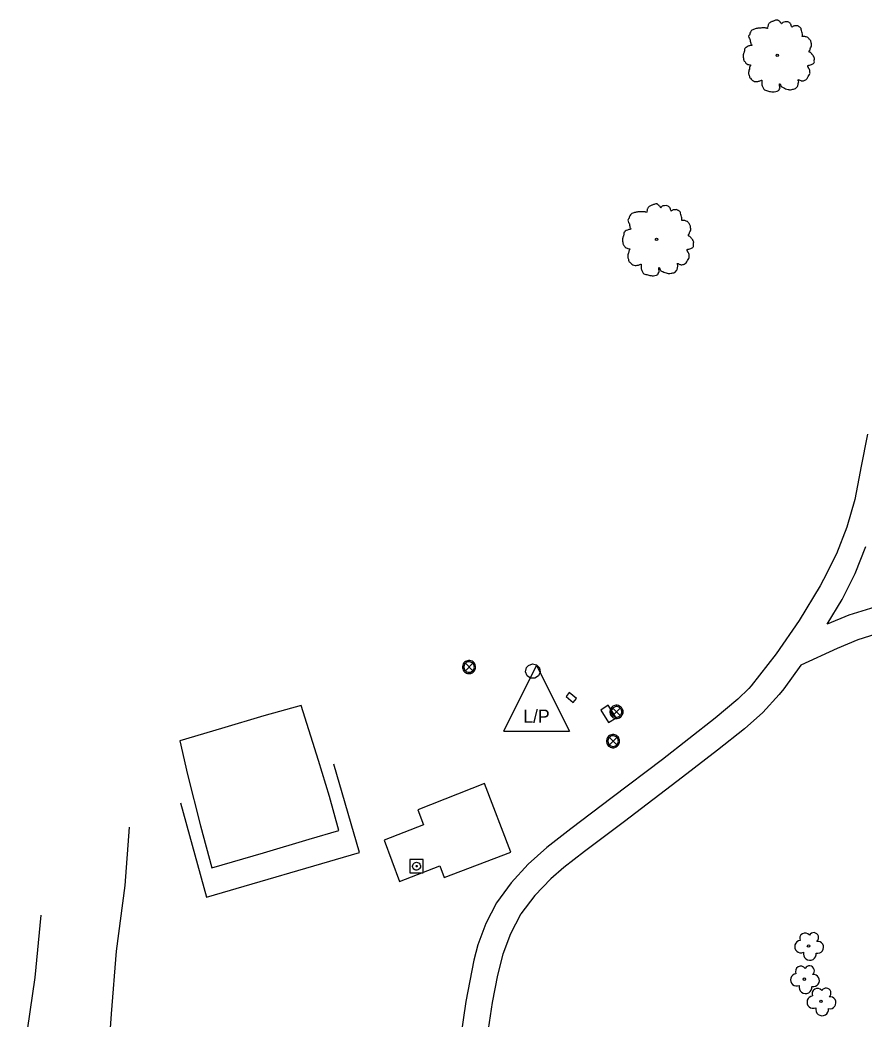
# Model space of a CAD drawing. Extents: x 2161152 to 2175754, y 602179 to 617749.
# Drawn here: x 2162053.8 to 2162182.3, y 604496.4 to 604648.6 of the extents above; entities that cross this region are included whole.
import ezdxf

# ---------------------------------------------------------------- set-up
doc = ezdxf.new("R2010")
doc.units = 0
for name, color, linetype in [('RD_EX_BldgApp', 7, 'Continuous'), ('RD_EX_BldgApp_Post', 7, 'Continuous'), ('RD_EX_Conc_Sidewalk', 7, 'Continuous'), ('RD_EX_Conc_Slab', 7, 'Continuous'), ('RD_EX_Fence_Other', 7, 'Continuous'), ('RD_EX_Misc', 7, 'Continuous'), ('RD_EX_Parking_Asphalt', 7, 'Continuous'), ('RD_EX_UT', 7, 'Continuous'), ('RD_EX_VEG', 7, 'Continuous')]:
    doc.layers.add(name, color=color, linetype=linetype)

msp = doc.modelspace()

# ---------------------------------------------------------------- linework, layer by layer
at = {"layer": 'RD_EX_BldgApp'}
msp.add_lwpolyline([(2162132.75, 604548.7), (2162132.21, 604548.34), (2162131.55, 604548.34), (2162131.02, 604548.71), (2162130.78, 604549.32), (2162130.92, 604549.95), (2162131.22, 604550.29), (2162131.83, 604550.52), (2162132.46, 604550.37), (2162132.9, 604549.89), (2162132.99, 604549.24), (2162132.75, 604548.7)], dxfattribs=at)
at = {"layer": 'RD_EX_BldgApp_Post'}
for p, q in [((2162122.75, 604549.47), (2162121.62, 604550.6)), ((2162121.62, 604549.47), (2162122.75, 604550.6)), ((2162145.21, 604542.64), (2162144.07, 604543.78)), ((2162144.07, 604542.64), (2162145.21, 604543.78)), ((2162144.68, 604538.18), (2162143.55, 604539.32)), ((2162143.55, 604538.18), (2162144.68, 604539.32))]:
    msp.add_line(p, q, dxfattribs=at)
for points in [[(2162123.19, 604550.03), (2162123.18, 604550.19), (2162123.14, 604550.35), (2162123.06, 604550.51), (2162122.96, 604550.67), (2162122.82, 604550.81), (2162122.66, 604550.92), (2162122.48, 604550.99), (2162122.29, 604551.03), (2162122.1, 604551.03), (2162121.93, 604551), (2162121.78, 604550.95), (2162121.64, 604550.87), (2162121.51, 604550.78), (2162121.4, 604550.65), (2162121.3, 604550.5), (2162121.23, 604550.32), (2162121.19, 604550.13), (2162121.19, 604549.93), (2162121.23, 604549.74), (2162121.3, 604549.57), (2162121.4, 604549.41), (2162121.51, 604549.29), (2162121.64, 604549.19), (2162121.78, 604549.12), (2162121.93, 604549.06), (2162122.1, 604549.03), (2162122.29, 604549.04), (2162122.48, 604549.07), (2162122.66, 604549.15), (2162122.82, 604549.26), (2162122.96, 604549.4), (2162123.06, 604549.55), (2162123.14, 604549.72), (2162123.18, 604549.88), (2162123.19, 604550.03)], [(2162122.99, 604550.03), (2162122.98, 604550.16), (2162122.95, 604550.29), (2162122.89, 604550.42), (2162122.8, 604550.54), (2162122.69, 604550.65), (2162122.56, 604550.74), (2162122.42, 604550.8), (2162122.27, 604550.83), (2162122.12, 604550.83), (2162121.98, 604550.81), (2162121.86, 604550.76), (2162121.75, 604550.71), (2162121.65, 604550.63), (2162121.56, 604550.53), (2162121.48, 604550.41), (2162121.42, 604550.27), (2162121.39, 604550.11), (2162121.39, 604549.95), (2162121.42, 604549.8), (2162121.48, 604549.66), (2162121.56, 604549.54), (2162121.65, 604549.44), (2162121.75, 604549.36), (2162121.86, 604549.3), (2162121.98, 604549.26), (2162122.12, 604549.23), (2162122.27, 604549.24), (2162122.42, 604549.27), (2162122.56, 604549.33), (2162122.69, 604549.41), (2162122.8, 604549.52), (2162122.89, 604549.65), (2162122.95, 604549.78), (2162122.98, 604549.91), (2162122.99, 604550.03)], [(2162145.64, 604543.21), (2162145.63, 604543.36), (2162145.59, 604543.53), (2162145.52, 604543.69), (2162145.41, 604543.85), (2162145.28, 604543.98), (2162145.11, 604544.09), (2162144.93, 604544.17), (2162144.74, 604544.21), (2162144.56, 604544.21), (2162144.38, 604544.18), (2162144.23, 604544.12), (2162144.1, 604544.05), (2162143.97, 604543.95), (2162143.85, 604543.83), (2162143.75, 604543.68), (2162143.68, 604543.5), (2162143.64, 604543.31), (2162143.64, 604543.11), (2162143.68, 604542.92), (2162143.75, 604542.74), (2162143.85, 604542.59), (2162143.97, 604542.46), (2162144.1, 604542.37), (2162144.23, 604542.29), (2162144.38, 604542.24), (2162144.56, 604542.21), (2162144.74, 604542.21), (2162144.93, 604542.25), (2162145.11, 604542.32), (2162145.28, 604542.43), (2162145.41, 604542.57), (2162145.52, 604542.73), (2162145.59, 604542.89), (2162145.63, 604543.05), (2162145.64, 604543.21)], [(2162145.44, 604543.21), (2162145.43, 604543.33), (2162145.4, 604543.46), (2162145.34, 604543.59), (2162145.26, 604543.72), (2162145.15, 604543.83), (2162145.02, 604543.92), (2162144.87, 604543.98), (2162144.72, 604544.01), (2162144.57, 604544.01), (2162144.44, 604543.98), (2162144.31, 604543.94), (2162144.21, 604543.88), (2162144.1, 604543.81), (2162144.01, 604543.71), (2162143.93, 604543.58), (2162143.87, 604543.44), (2162143.84, 604543.29), (2162143.84, 604543.13), (2162143.87, 604542.98), (2162143.93, 604542.84), (2162144.01, 604542.71), (2162144.1, 604542.61), (2162144.21, 604542.54), (2162144.31, 604542.48), (2162144.44, 604542.43), (2162144.57, 604542.41), (2162144.72, 604542.41), (2162144.87, 604542.44), (2162145.02, 604542.5), (2162145.15, 604542.59), (2162145.26, 604542.7), (2162145.34, 604542.82), (2162145.4, 604542.96), (2162145.43, 604543.09), (2162145.44, 604543.21)], [(2162145.12, 604538.75), (2162145.1, 604538.9), (2162145.07, 604539.07), (2162144.99, 604539.23), (2162144.89, 604539.39), (2162144.75, 604539.52), (2162144.59, 604539.63), (2162144.4, 604539.71), (2162144.22, 604539.75), (2162144.03, 604539.75), (2162143.86, 604539.72), (2162143.7, 604539.66), (2162143.57, 604539.59), (2162143.44, 604539.49), (2162143.33, 604539.37), (2162143.23, 604539.22), (2162143.15, 604539.04), (2162143.12, 604538.85), (2162143.12, 604538.65), (2162143.15, 604538.46), (2162143.23, 604538.28), (2162143.33, 604538.13), (2162143.44, 604538), (2162143.57, 604537.91), (2162143.7, 604537.84), (2162143.86, 604537.78), (2162144.03, 604537.75), (2162144.22, 604537.75), (2162144.4, 604537.79), (2162144.59, 604537.87), (2162144.75, 604537.98), (2162144.89, 604538.11), (2162144.99, 604538.27), (2162145.07, 604538.43), (2162145.1, 604538.6), (2162145.12, 604538.75)], [(2162144.92, 604538.75), (2162144.91, 604538.87), (2162144.87, 604539), (2162144.82, 604539.13), (2162144.73, 604539.26), (2162144.62, 604539.37), (2162144.49, 604539.46), (2162144.35, 604539.52), (2162144.2, 604539.55), (2162144.05, 604539.55), (2162143.91, 604539.53), (2162143.79, 604539.48), (2162143.68, 604539.42), (2162143.58, 604539.35), (2162143.48, 604539.25), (2162143.4, 604539.12), (2162143.35, 604538.98), (2162143.32, 604538.83), (2162143.32, 604538.67), (2162143.35, 604538.52), (2162143.4, 604538.38), (2162143.48, 604538.25), (2162143.58, 604538.15), (2162143.68, 604538.08), (2162143.79, 604538.02), (2162143.91, 604537.97), (2162144.05, 604537.95), (2162144.2, 604537.95), (2162144.35, 604537.98), (2162144.49, 604538.04), (2162144.62, 604538.13), (2162144.73, 604538.24), (2162144.82, 604538.37), (2162144.87, 604538.5), (2162144.91, 604538.63), (2162144.92, 604538.75)]]:
    msp.add_lwpolyline(points, dxfattribs=at)
at = {"layer": 'RD_EX_Conc_Sidewalk'}
for points in [[(2162182.89, 604585.49), (2162181.85, 604580.4), (2162181.76, 604579.84), (2162180.92, 604575.56), (2162179.7, 604571.36), (2162178.12, 604567.29), (2162176.19, 604563.38), (2162175.64, 604562.41), (2162172.46, 604557.12), (2162168.95, 604552.04), (2162165.14, 604547.19), (2162164.79, 604546.78), (2162163.13, 604545.12), (2162159.67, 604542.24), (2162151.66, 604535.96), (2162143.97, 604530.16), (2162137.67, 604525.39), (2162134.03, 604522.54), (2162131.18, 604520), (2162128.61, 604517.17), (2162126.34, 604514.1), (2162124.75, 604510.99), (2162123.53, 604507.73), (2162122.89, 604505.36), (2162121.7, 604499.1), (2162120.07, 604487.93)], [(2162183.99, 604559.14), (2162180.04, 604557.93), (2162176.72, 604556.54), (2162179.02, 604560.31), (2162180.99, 604564.27), (2162182.62, 604568.38)], [(2162184.94, 604555.28), (2162181.39, 604554.2), (2162178.25, 604552.88), (2162172.69, 604550.3), (2162170.11, 604546.73), (2162169.43, 604545.87), (2162166.92, 604543.11), (2162164.13, 604540.62), (2162160.02, 604537.36), (2162154.69, 604533.24), (2162145.85, 604526.49), (2162139.77, 604521.91), (2162136.62, 604519.49), (2162134.65, 604517.78), (2162132.22, 604515.23), (2162130.09, 604512.43), (2162130.03, 604512.32), (2162128.49, 604509.4), (2162127.31, 604506.31), (2162126.51, 604503.11), (2162125.68, 604498.95), (2162124.2, 604488.77)]]:
    msp.add_lwpolyline(points, dxfattribs=at)
at = {"layer": 'RD_EX_Conc_Slab'}
for points in [[(2162078.14, 604538.81), (2162079.29, 604533.65), (2162081.26, 604525.82), (2162083.03, 604519.46), (2162090.89, 604521.73), (2162097.82, 604523.82), (2162102.33, 604525.14), (2162100.92, 604530.32), (2162099.24, 604535.8), (2162096.63, 604544.18), (2162090.94, 604542.59), (2162084.5, 604540.69), (2162078.14, 604538.81)], [(2162109.28, 604523.66), (2162111.57, 604517.37), (2162117.72, 604519.76), (2162118.4, 604517.98), (2162128.57, 604521.83), (2162124.52, 604532.29), (2162114.37, 604528.29), (2162115.24, 604526), (2162109.28, 604523.66)]]:
    msp.add_lwpolyline(points, dxfattribs=at)
at = {"layer": 'RD_EX_Fence_Other'}
msp.add_lwpolyline([(2162078.24, 604529.36), (2162082.18, 604515), (2162105.52, 604521.77), (2162101.59, 604535.26)], dxfattribs=at)
at = {"layer": 'RD_EX_Misc'}
for points in [[(2162113.19, 604518.7), (2162115.19, 604518.7), (2162115.19, 604520.7), (2162113.19, 604520.7), (2162113.19, 604518.7)], [(2162113.59, 604519.7), (2162113.61, 604519.85), (2162113.67, 604519.99), (2162113.76, 604520.11), (2162113.88, 604520.21), (2162114.02, 604520.27), (2162114.17, 604520.3), (2162114.32, 604520.28), (2162114.47, 604520.23), (2162114.59, 604520.14), (2162114.69, 604520.02), (2162114.76, 604519.88), (2162114.79, 604519.73), (2162114.79, 604519.7)], [(2162114.79, 604519.7), (2162114.77, 604519.54), (2162114.71, 604519.4), (2162114.62, 604519.28), (2162114.5, 604519.18), (2162114.36, 604519.12), (2162114.21, 604519.1), (2162114.06, 604519.11), (2162113.91, 604519.16), (2162113.79, 604519.25), (2162113.69, 604519.37), (2162113.62, 604519.51), (2162113.59, 604519.66), (2162113.59, 604519.7)], [(2162114.09, 604519.7), (2162114.11, 604519.75), (2162114.16, 604519.79), (2162114.22, 604519.79), (2162114.27, 604519.75), (2162114.29, 604519.7)], [(2162114.29, 604519.7), (2162114.27, 604519.64), (2162114.22, 604519.6), (2162114.16, 604519.6), (2162114.11, 604519.64), (2162114.09, 604519.7)]]:
    msp.add_lwpolyline(points, dxfattribs=at)
at = {"layer": 'RD_EX_Parking_Asphalt'}
for points in [[(2162066.8, 604484.24), (2162067.74, 604497.21), (2162068.47, 604506.77), (2162069.79, 604516.75), (2162070.47, 604525.63)], [(2162056.95, 604512.25), (2162056.05, 604502.75), (2162053.79, 604487.07)]]:
    msp.add_lwpolyline(points, dxfattribs=at)
at = {"layer": 'RD_EX_UT'}
for p, q in [((2162127.46, 604540.27), (2162132.46, 604550.27)), ((2162132.46, 604550.27), (2162137.46, 604540.27)), ((2162127.46, 604540.27), (2162137.46, 604540.27))]:
    msp.add_line(p, q, dxfattribs=at)
for points in [[(2162136.96, 604545.54), (2162138.06, 604544.65), (2162138.56, 604545.26), (2162137.45, 604546.15), (2162136.96, 604545.54)], [(2162142.23, 604543.48), (2162143.43, 604541.57), (2162144.59, 604542.29), (2162143.39, 604544.21), (2162142.23, 604543.48)]]:
    msp.add_lwpolyline(points, dxfattribs=at)
at = {"layer": 'RD_EX_VEG'}
for centre, radius in [((2162169.12, 604643.2), 0.188), ((2162169.11, 604643.18), 0.000075), ((2162150.74, 604615.19), 0.188), ((2162150.73, 604615.18), 0.000075), ((2162173.89, 604507.55), 0.188), ((2162173.25, 604502.49), 0.188), ((2162175.77, 604499.11), 0.188)]:
    msp.add_circle(centre, radius, dxfattribs=at)
for centre, radius, start, end in [((2162173.35, 604508.71), 0.813, 34.9763, 204.756), ((2162174.68, 604508.83), 0.746, 308.7626, 152.0467), ((2162172.72, 604507.44), 0.943, 96.4518, 294.734), ((2162175.27, 604507.34), 0.914, 256.5667, 98.1046), ((2162174.08, 604506.36), 0.988, 166.8827, 5.7589), ((2162174.03, 604503.77), 0.746, 308.7626, 152.0467), ((2162172.08, 604502.38), 0.943, 96.4518, 294.734), ((2162172.71, 604503.65), 0.813, 34.9763, 204.756), ((2162174.63, 604502.28), 0.914, 256.5667, 98.1046), ((2162173.43, 604501.29), 0.988, 166.8827, 5.7589), ((2162174.6, 604498.99), 0.943, 96.4518, 294.734), ((2162175.23, 604500.27), 0.813, 34.9763, 204.756), ((2162176.56, 604500.38), 0.746, 308.7626, 152.0467), ((2162177.15, 604498.9), 0.914, 256.5667, 98.1046), ((2162175.96, 604497.91), 0.988, 166.8827, 5.7589)]:
    msp.add_arc(centre, radius, start, end, dxfattribs=at)
for points in [[(2162169.22, 604648.57), (2162168.99, 604648.59), (2162168.75, 604648.52), (2162168.56, 604648.44), (2162168.39, 604648.39), (2162168.23, 604648.31), (2162168, 604648.18), (2162167.83, 604648.03), (2162167.74, 604647.84), (2162167.7, 604647.67), (2162167.66, 604647.47), (2162167.66, 604647.34), (2162167.57, 604647.32), (2162167.46, 604647.34), (2162167.27, 604647.39), (2162167.08, 604647.39), (2162166.9, 604647.39), (2162166.63, 604647.37), (2162166.37, 604647.37), (2162166.16, 604647.34), (2162165.92, 604647.3), (2162165.64, 604647.2), (2162165.38, 604647.11), (2162165.15, 604646.92), (2162164.96, 604646.57), (2162164.87, 604646.3), (2162164.76, 604646.12), (2162164.87, 604645.78), (2162165, 604645.52), (2162165.02, 604645.37), (2162165.08, 604645.05), (2162165.15, 604644.88), (2162165.25, 604644.73), (2162165.19, 604644.71), (2162164.91, 604644.67), (2162164.68, 604644.6), (2162164.37, 604644.43), (2162164.2, 604644.26), (2162164.12, 604644.02), (2162164.1, 604643.76), (2162164.03, 604643.61), (2162163.97, 604643.4), (2162163.95, 604643.34), (2162163.92, 604643.1), (2162163.99, 604642.76), (2162164.01, 604642.5), (2162164.1, 604642.33), (2162164.22, 604642.2), (2162164.35, 604642.01), (2162164.65, 604641.84), (2162164.89, 604641.77), (2162165.04, 604641.75), (2162164.91, 604641.38), (2162164.87, 604641.11), (2162164.78, 604640.81), (2162164.78, 604640.76), (2162164.74, 604640.4), (2162164.85, 604640.16), (2162164.91, 604639.88), (2162165.04, 604639.71), (2162165.25, 604639.48), (2162165.49, 604639.31), (2162165.86, 604639.22), (2162166.16, 604639.24), (2162166.6, 604639.37), (2162166.78, 604639.43), (2162166.76, 604639.3), (2162166.78, 604639.01), (2162166.78, 604638.7), (2162166.9, 604638.45), (2162166.97, 604638.25), (2162167.08, 604638.06), (2162167.33, 604637.89), (2162167.63, 604637.83), (2162167.94, 604637.72), (2162168.28, 604637.66), (2162168.66, 604637.65), (2162169.11, 604637.76), (2162169.31, 604637.85), (2162169.39, 604637.98), (2162169.54, 604638.26), (2162169.5, 604638.43), (2162169.52, 604638.88), (2162169.59, 604638.75), (2162169.73, 604638.49), (2162170.1, 604638.26), (2162170.4, 604638.13), (2162170.76, 604638.02), (2162170.98, 604637.96), (2162171.34, 604638.02), (2162171.62, 604638.08), (2162171.9, 604638.17), (2162172.12, 604638.38), (2162172.26, 604638.58), (2162172.29, 604638.79), (2162172.35, 604639.07), (2162172.39, 604639.2)], [(2162172.39, 604639.2), (2162172.33, 604639.33), (2162172.29, 604639.52), (2162172.35, 604639.5), (2162172.48, 604639.46), (2162172.69, 604639.37), (2162172.86, 604639.31), (2162173.1, 604639.33), (2162173.31, 604639.41), (2162173.64, 604639.61), (2162173.85, 604639.97), (2162174.05, 604640.27), (2162174.11, 604640.51), (2162174.07, 604640.68), (2162174.05, 604641.06), (2162173.9, 604641.24), (2162173.87, 604641.34), (2162173.79, 604641.64), (2162173.85, 604641.68), (2162174.05, 604641.71), (2162174.34, 604641.81), (2162174.54, 604641.9), (2162174.71, 604642.03), (2162174.77, 604642.2), (2162174.75, 604642.5), (2162174.79, 604642.8), (2162174.73, 604642.91), (2162174.65, 604643.02), (2162174.6, 604643.17), (2162174.49, 604643.29), (2162174.41, 604643.4), (2162174.34, 604643.47), (2162174.24, 604643.59), (2162174.11, 604643.68), (2162174, 604643.72), (2162173.96, 604643.83), (2162174.07, 604643.98), (2162174.11, 604644.06), (2162174.13, 604644.22), (2162174.3, 604644.49), (2162174.34, 604644.79), (2162174.3, 604645.11), (2162174.26, 604645.31), (2162174.15, 604645.52), (2162174, 604645.7), (2162173.9, 604645.84), (2162173.77, 604645.93), (2162173.53, 604646.02), (2162173.34, 604646.06), (2162173.08, 604646.06), (2162172.93, 604646.1), (2162172.95, 604646.14), (2162172.95, 604646.25), (2162172.95, 604646.45), (2162172.89, 604646.79), (2162172.78, 604647.17), (2162172.78, 604647.19), (2162172.71, 604647.37), (2162172.54, 604647.52), (2162172.41, 604647.6), (2162172.26, 604647.69), (2162172.07, 604647.71), (2162171.84, 604647.71), (2162171.64, 604647.67), (2162171.49, 604647.6), (2162171.36, 604647.5), (2162171.3, 604647.62), (2162171.22, 604647.84), (2162171.19, 604647.95), (2162171.07, 604648.09), (2162170.91, 604648.24), (2162170.57, 604648.33), (2162170.1, 604648.27), (2162169.88, 604648.12), (2162169.76, 604647.99), (2162169.73, 604648.09), (2162169.58, 604648.24), (2162169.5, 604648.37), (2162169.37, 604648.46), (2162169.26, 604648.53), (2162169.18, 604648.57)], [(2162150.84, 604620.57), (2162150.61, 604620.58), (2162150.37, 604620.51), (2162150.18, 604620.43), (2162150.01, 604620.38), (2162149.84, 604620.3), (2162149.62, 604620.17), (2162149.45, 604620.02), (2162149.35, 604619.84), (2162149.32, 604619.67), (2162149.28, 604619.46), (2162149.28, 604619.33), (2162149.19, 604619.31), (2162149.07, 604619.33), (2162148.89, 604619.39), (2162148.7, 604619.39), (2162148.51, 604619.39), (2162148.25, 604619.37), (2162147.99, 604619.37), (2162147.78, 604619.33), (2162147.54, 604619.29), (2162147.26, 604619.2), (2162146.99, 604619.1), (2162146.77, 604618.92), (2162146.58, 604618.56), (2162146.49, 604618.3), (2162146.37, 604618.11), (2162146.49, 604617.77), (2162146.62, 604617.51), (2162146.64, 604617.36), (2162146.69, 604617.04), (2162146.77, 604616.87), (2162146.86, 604616.72), (2162146.81, 604616.71), (2162146.52, 604616.67), (2162146.3, 604616.59), (2162145.98, 604616.42), (2162145.81, 604616.26), (2162145.74, 604616.01), (2162145.72, 604615.75), (2162145.64, 604615.6), (2162145.59, 604615.39), (2162145.57, 604615.34), (2162145.53, 604615.09), (2162145.61, 604614.76), (2162145.63, 604614.49), (2162145.72, 604614.33), (2162145.83, 604614.19), (2162145.96, 604614.01), (2162146.26, 604613.84), (2162146.51, 604613.76), (2162146.66, 604613.74), (2162146.52, 604613.37), (2162146.49, 604613.11), (2162146.39, 604612.81), (2162146.39, 604612.75), (2162146.36, 604612.39), (2162146.47, 604612.15), (2162146.52, 604611.87), (2162146.66, 604611.7), (2162146.86, 604611.48), (2162147.11, 604611.31), (2162147.48, 604611.21), (2162147.78, 604611.23), (2162148.21, 604611.36), (2162148.4, 604611.42), (2162148.38, 604611.29), (2162148.4, 604611.01), (2162148.4, 604610.69), (2162148.51, 604610.45), (2162148.59, 604610.24), (2162148.7, 604610.05), (2162148.94, 604609.88), (2162149.24, 604609.83), (2162149.56, 604609.71), (2162149.9, 604609.66), (2162150.27, 604609.64), (2162150.72, 604609.75), (2162150.93, 604609.85), (2162151, 604609.98), (2162151.15, 604610.26), (2162151.12, 604610.43), (2162151.14, 604610.88), (2162151.21, 604610.75), (2162151.34, 604610.48), (2162151.72, 604610.26), (2162152.02, 604610.13), (2162152.37, 604610.01), (2162152.6, 604609.96), (2162152.95, 604610.01), (2162153.23, 604610.07), (2162153.52, 604610.16), (2162153.74, 604610.37), (2162153.87, 604610.58), (2162153.91, 604610.78), (2162153.97, 604611.06), (2162154, 604611.2)], [(2162154, 604611.2), (2162153.95, 604611.33), (2162153.91, 604611.51), (2162153.97, 604611.5), (2162154.1, 604611.46), (2162154.3, 604611.36), (2162154.47, 604611.31), (2162154.72, 604611.33), (2162154.92, 604611.4), (2162155.26, 604611.61), (2162155.46, 604611.96), (2162155.67, 604612.26), (2162155.73, 604612.51), (2162155.69, 604612.68), (2162155.67, 604613.05), (2162155.52, 604613.24), (2162155.48, 604613.33), (2162155.41, 604613.63), (2162155.46, 604613.67), (2162155.67, 604613.71), (2162155.95, 604613.8), (2162156.16, 604613.89), (2162156.33, 604614.03), (2162156.38, 604614.19), (2162156.36, 604614.49), (2162156.4, 604614.79), (2162156.35, 604614.91), (2162156.27, 604615.02), (2162156.21, 604615.17), (2162156.1, 604615.28), (2162156.03, 604615.39), (2162155.95, 604615.47), (2162155.86, 604615.58), (2162155.73, 604615.67), (2162155.61, 604615.71), (2162155.58, 604615.82), (2162155.69, 604615.97), (2162155.73, 604616.05), (2162155.75, 604616.22), (2162155.91, 604616.48), (2162155.95, 604616.78), (2162155.91, 604617.1), (2162155.88, 604617.31), (2162155.76, 604617.51), (2162155.61, 604617.7), (2162155.52, 604617.83), (2162155.39, 604617.92), (2162155.15, 604618.02), (2162154.96, 604618.05), (2162154.7, 604618.05), (2162154.55, 604618.09), (2162154.57, 604618.13), (2162154.57, 604618.24), (2162154.57, 604618.45), (2162154.51, 604618.79), (2162154.4, 604619.16), (2162154.4, 604619.18), (2162154.32, 604619.37), (2162154.15, 604619.52), (2162154.02, 604619.59), (2162153.87, 604619.69), (2162153.68, 604619.7), (2162153.46, 604619.7), (2162153.25, 604619.67), (2162153.1, 604619.59), (2162152.97, 604619.5), (2162152.92, 604619.61), (2162152.84, 604619.84), (2162152.8, 604619.95), (2162152.69, 604620.08), (2162152.52, 604620.23), (2162152.18, 604620.32), (2162151.72, 604620.27), (2162151.49, 604620.12), (2162151.38, 604619.99), (2162151.34, 604620.08), (2162151.19, 604620.23), (2162151.12, 604620.36), (2162150.99, 604620.45), (2162150.87, 604620.53), (2162150.8, 604620.57)]]:
    msp.add_spline(points, degree=3, dxfattribs=at)

# ---------------------------------------------------------------- texts
at = {"layer": 'RD_EX_UT'}
msp.add_text('L/P', height=2, dxfattribs=at).set_placement((2162130.45, 604541.55))

doc.saveas('drawing.dxf')
